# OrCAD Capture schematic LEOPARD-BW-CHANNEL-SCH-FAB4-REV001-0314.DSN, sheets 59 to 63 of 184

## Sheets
59 130_P12V_PCIE_HDD: size A3; title: P12V_PCIE_HDD
60 129_HOT SWAP CIRCUIT: size A2; title: HOT SWAP CIRCUIT
61 128_FAST PROCHOT: size Custom; title: FAST PROCHOT
62 127_INTEL I210 DECOUPLING: size A3; title: INTEL I210 DECOUPLING
63 126_INTEL I210 - RJ45: size A3; title: INTEL I210 - RJ45

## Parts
sheet 126_INTEL I210 - RJ45
C324  SCD1U16V2KX-3GP  [C402H22]
C325  SCD1U16V2KX-3GP  [C402H22]
C326  SCD1U16V2KX-3GP  [C402H22]
C329  SCD1U16V2KX-3GP  [C402H22]
C330  SCD1U16V2KX-3GP  [C402H22]
C331  SCD1U16V2KX-3GP  [C402H22]
C336  SCD1U16V2KX-3GP  [C402H22]
C337  SCD1U16V2KX-3GP  [C402H22]
C338  SCD1U16V2KX-3GP  [C402H22]
D39  PGB1010603MR-GP  [L1608-UH15]
D40  PGB1010603MR-GP  [L1608-UH15]
D41  PGB1010603MR-GP  [L1608-UH15]
D42  PGB1010603MR-GP  [L1608-UH15]
D43  PGB1010603MR-GP  [L1608-UH15]
D44  PGB1010603MR-GP  [L1608-UH15]
D45  PGB1010603MR-GP  [L1608-UH15]
D46  PGB1010603MR-GP  [L1608-UH15]
R1016  150R2J-L1-GP-U  [R402H16]
R1017  150R2J-L1-GP-U  [R402H16]
R1018  0R2J-2-GP  [R402H16]
R1019  0R2J-2-GP  [R402H16]
R1020  0R2J-2-GP  [R402H16]
R1021  0R2J-2-GP  [R402H16]
R1022  0R2J-2-GP  [R402H16]
R1023  0R2J-2-GP  [R402H16]
R1025  0R2J-2-GP  [R402H16]
R1026  0R2J-2-GP  [R402H16]
R1029  0R2J-2-GP  [R402H16]
R1030  0R2J-2-GP  [R402H16]
R1031  0R2J-2-GP  [R402H16]
R1032  0R2J-2-GP  [R402H16]
R2160  150R3J-L-GP  [R603H22]
R2161  150R3J-L-GP  [R603H22]
RJ1  RJ45-LED-12P-10-GP  [XRJH-01H-D-H71-D81-W]
sheet 127_INTEL I210 DECOUPLING
C7295  SC47U4V5MX-2-GP  [C805H58]
C7296  SC10U6D3V5KX-4GP  [C805H58]
C7297  SC10U6D3V5KX-4GP  [C805H58]
C7298  SCD1U16V2KX-3GP  [C402H22]
C7299  SCD1U16V2KX-3GP  [C402H22]
C7300  SCD1U16V2KX-3GP  [C402H22]
C7301  SCD1U16V2KX-3GP  [C402H22]
C7302  SC47U4V5MX-2-GP  [C805H58]
C7303  SC10U6D3V5KX-4GP  [C805H58]
C7304  SCD1U16V2KX-3GP  [C402H22]
C7305  SCD1U16V2KX-3GP  [C402H22]
C7306  SCD1U16V2KX-3GP  [C402H22]
C7307  SCD1U16V2KX-3GP  [C402H22]
C7308  SC10U6D3V5KX-4GP  [C805H58]
C7309  SC47U4V5MX-2-GP  [C805H58]
C7310  SC10U6D3V5KX-4GP  [C805H58]
C7311  SCD1U16V2KX-3GP  [C402H22]
C7312  SCD1U16V2KX-3GP  [C402H22]
C7313  SCD1U16V2KX-3GP  [C402H22]
C7314  SCD1U16V2KX-3GP  [C402H22]
C7315  SC10U6D3V5KX-4GP  [C805H58]
sheet 128_FAST PROCHOT
C112  SC10U6D3V5KX-4GP  [C805H58]
C316  SC100P50V2JN-3GP  [C402H22]
C356  SC100P50V2JN-3GP  [C402H22]
C371  SCD1U16V2KX-3GP  [C402H22]
C373  SC100P50V2JN-3GP  [C402H22]
C374  SCD1U16V2KX-3GP  [C402H22]
C376  SCD1U16V2KX-3GP  [C402H22]
C377  SCD1U16V2KX-3GP  [C402H22]
C378  SCD1U16V2KX-3GP  [C402H22]
C379  SCD1U16V2KX-3GP  [C402H22]
D38  TL431IDBZR-GP  [SOT-23-1H45]
Q19  2N7002-7F-GP  [SOT23DGS2D4H44]
R128  464R2F-GP  [R402H16]
R145  27KR2F-L-GP  [R402H16]
R169  11K5R2F-GP  [R402H16]
R249  3K24R2F-GP  [R402H16]
R264  7K5R2F-1-GP  [R402H16]
R266  10KR2F-2-GP  [R402H16]
R267  3K16R2F-GP  [R402H16]
R269  3K9R2F-GP  [R402H16]
R289  20KR2F-L-GP  [R402H16]
R290  10KR2F-2-GP  [R402H16]
R339  4K7R2F-GP  [R402H16]
R340  4K7R2F-GP  [R402H16]
R350  27KR2F-L-GP  [R402H16]
R380  0R2J-2-GP  [R402H16]
R403  1MR2F-GP  [R402H16]
R404  0R2J-2-GP  [R402H16]
R406  1MR2F-GP  [R402H16]
R416  10KR2F-2-GP  [R402H16]
R417  0R2J-2-GP  [R402H16]
R420  1MR2F-GP  [R402H16]
R423  10KR2F-2-GP  [R402H16]
R533  1MR2F-GP  [R402H16]
R727  100R3J-4-GP  [R603H22]
R1590  10KR2F-2-GP  [R402H16]
R1591  10KR2F-2-GP  [R402H16]
U34  LM393DR-GP  [SOIC8H69]
U50  LM393DR-GP  [SOIC8H69]
U52  NTJD4001NT1G-1-GP  [SOT-363H44]
U53  NTJD4001NT1G-1-GP  [SOT-363H44]
sheet 129_HOT SWAP CIRCUIT
C160  SC1U10V2KX-4-GP  [C402H22]
C375  SCD015U25V2KX-GP  [C402H22]
C478  SC1KP50V2KX-1GP  [C402H22]
C7272  SCD1U16V2KX-3GP  [C402H22]
C7273  SCD022U25V2KX-GP  [C402H22]
C7274  SCD1U25V3KX-GP  [C603H36]
C7275  SC1U10V2KX-4-GP  [C402H22]
C7276  SC1U10V2KX-4-GP  [C402H22]
C7277  SC1U16V3KX-5GP  [C603H36]
C7278  SCD1U25V3JX-GP  [C603H36]
C7279  SCD033U50V3KX-1GP  [C603H36]
C7316  SCD1U25V3JX-GP  [C603H36]
C7317  SCD1U25V3JX-GP  [C603H36]
D7  SMCJ13A-GP  [D795930AKH104]
JP2  FCI-CON3-S1-GP  [68001-203HLF]
P2121  0R0603-PAD-2-GP-U  [0R0603-PAD-1-U]
PC1083  SC1U25V3KX-GP  [C603H36]
PQ33  NST3904F3T5G-GP-U  [SOT-1123CBE1006H16]
Q8  PH0925CL-GP  [LFPAK-5PH48-U]
Q25  2N7002-7F-GP  [SOT23DGS2D4H44]
Q90  PH0925CL-GP  [LFPAK-5PH48-U]
R148  0R2J-2-GP  [R402H16]
R199  100R2F-L1-GP-U  [R402H14]
R250  0R2J-2-GP  [R402H16]
R255  100R2F-L1-GP-U  [R402H14]
R270  PAD-D001R2512F-6P-GP  [PAD-R2512-2032H36-6P]
R342  PAD-D001R2512F-6P-GP  [PAD-R2512-2032H36-6P]
R345  0R2J-2-GP  [R402H16]
R395  0R2J-2-GP  [R402H16]
R396  0R2J-2-GP  [R402H16]
R408  88K7R2F-GP  [R402H16]
R532  10KR2J-3-GP  [R402H16]
R674  10KR2F-2-GP  [R402H16]
R726  10KR2F-2-GP  [R402H16]
R763  6K65R2F-GP  [R402H16]
R1226  12K1R2F-L1-GP  [R402H16]
R1227  100KR2F-L1-GP  [R402H16]
R2015  10KR2F-2-GP  [R402H16]
R2098  10R2F-L-GP  [R402H14]
R2099  39K2R2F-L-GP  [R402H16]
R2100  0R2J-2-GP  [R402H16]
R2101  0R2J-2-GP  [R402H16]
R2102  26K1R2F-2-GP  [R402H16]
R2103  150KR2J-GP  [R402H16]
R2106  49K9R2F-L-GP  [R402H16]
R2107  49K9R2F-L-GP  [R402H16]
R2108  3K74R2F-GP  [R402H16]
R2109  5K49R2F-GP  [R402H16]
R2110  1KR2J-1-GP  [R402H16]
R2111  10R2J-2-GP  [R402H14]
R2112  10R2J-2-GP  [R402H14]
R2113  0R2J-2-GP  [R402H16]
R2114  0R2J-2-GP  [R402H16]
R2117  100KR2F-L1-GP  [R402H16]
R2119  10R2F-L-GP  [R402H14]
R2120  10R2F-L-GP  [R402H14]
R2121  10R2F-L-GP  [R402H14]
R2122  10R2F-L-GP  [R402H14]
R2123  10R2F-L-GP  [R402H14]
R2171  100KR2J-1-GP  [R402H16]
R2172  0R2J-2-GP  [R402H16]
R2173  30K1R2F-L-GP  [R402H16]
R2174  100KR2J-1-GP  [R402H16]
R2175  25K5R2F-GP  [R402H16]
R6611  270KR2F-GP  [R402H16]
U2  ADM1278-1ACPZ-GP  [QFN32-G3D45-UH32]
sheet 130_P12V_PCIE_HDD
C37  SCD1U25V3KX-GP  [C603H36]
C40  SCD1U25V3KX-GP  [C603H36]
C42  SCD1U16V2KX-3GP  [C402H22]
C43  SCD1U16V2KX-3GP  [C402H22]
C44  SCD1U16V2KX-3GP  [C402H22]
C47  SCD1U16V2KX-3GP  [C402H22]
C48  SCD1U16V2KX-3GP  [C402H22]
C49  SCD1U16V2KX-3GP  [C402H22]
C50  SCD1U25V3KX-GP  [C603H36]
C732  SC1U25V3KX-GP  [C603H36]
Q22  PSMN4R4-30MLC-GP  [PPAK-8P-3333-1H40]
Q31  FDMS7572S-GP  [PPAK-5PH44]
Q32  PH0925CL-GP  [LFPAK-5PH48-U]
R182  49K9R2F-L-GP  [R402H16]
R184  49K9R2F-L-GP  [R402H16]
R189  0R2J-2-GP  [R402H16]
R341  49K9R2F-L-GP  [R402H16]
R346  1KR2J-1-GP  [R402H16]
R352  0R2J-2-GP  [R402H16]
R355  1KR2J-1-GP  [R402H16]
R356  0R2J-2-GP  [R402H16]
R360  100KR2J-1-GP  [R402H16]
R425  1KR2F-3-GP  [R402H16]
R740  49K9R2F-L-GP  [R402H16]
R749  49K9R2F-L-GP  [R402H16]
R750  0R2J-2-GP  [R402H16]
R774  49K9R2F-L-GP  [R402H16]
R789  0R2J-2-GP  [R402H16]
R1212  10KR2F-2-GP  [R402H16]
R1326  0R2J-2-GP  [R402H16]
R1327  0R2J-2-GP  [R402H16]
U18  SLG55021-130010VTR-GP  [DFN8G2-G165105H32]
U26  SLG55021-130010VTR-GP  [DFN8G2-G165105H32]
U27  ADM809SARTZ-REEL7-2-GP  [SOT23-2D4-312H49]
U47  SLG55021-130010VTR-GP  [DFN8G2-G165105H32]
U177  SNLVC1G08DCKRG4-GP  [SC70-5H44]

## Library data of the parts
C324-C326 C329-C331 C336-C338 = SCD1U16V2KX-3GP: CHIP CAP C 0.1U 16V K0402 X7R; Belong: POP; Category: RJ45 CONN; GREENDFACTOR: R_SA;; POP?: NOPOP; Part Number: 78.10421.2FL; Part Type: SMD-BCG; Quotation: 15_10; Type: SMD; Vendor PN: C1005X7R104KET/GRM155R71C104KA88D/223878715649/CL05B104KO5NNNC/EMK105BJ104KV-F/C1005X7R1C104KT000F/0402B104K160CT
D39-D46 = PGB1010603MR-GP: CHIP ESD SUPP PGB1010603NR SMD; GREENDFACTOR: R2_SA;HF_SA;; POP?: NOPOP; Part Number: 69.10059.031; Part Type: DISCRET-G4; SPEC: http://wpqssvr.wistron.com.tw:7001/wpqs/servlet/COM.qpart.Attachment?PartNumber=69.10059.031
R1016 R1017 = 150R2J-L1-GP-U: CHIP RES 150 J 1/16W 0402; Category: RJ45 CONN; GREENDFACTOR: R2_SA;HF_SA;G_SA;; POP?: NOPOP; Part Number: 63.15134.1DL; Part Type: SMD-RG; SPEC: http://wpqssvr.wistron.com.tw:7001/wpqs/servlet/COM.qpart.Attachment?PartNumber=63.15134.1DL
R1018-R1023 R1025 R1026 R1029-R1032 = 0R2J-2-GP: CHIP RES 0 J 1/16W 0402; Category: LOM - i350; DESCRIPTIO: CHIP RES 0 J 1/16W 0402; GREENDFACTOR: R2_SA;HF_SA;G_SA;; POP?: NOPOP; Package Type: SMD-RG; Part Number: 63.R0034.1DL; Part Type: SMD-RG; SPEC: http://wpqssvr.wistron.com.tw:7001/wpqs/servlet/COM.qpart.Attachment?PartNumber=63.R0034.1DL; VENDORPARTNUMBER: RM04JTN0/RTT02000JTH/RR0510X-000-XN/RC0402JR-070RL/WR04X000 PTL; Vendor PN: RM04JTN0/RTT02000JTH/RR0510X-000-XN/RC0402JR-070RL/WR04X000 PTL
R2160 R2161 = 150R3J-L-GP: CHIP RES 150 J 1/10W 0603; Category: RJ45 CONN; DESCRIPTIO: CHIP RES 150 J 1/10W 0603; GREENDFACTOR: R2_SA;HF_SA;G_SA;; Module: IO_REAR USB / LOM; POP?: NOPOP; Part Number: 63.15133.15L; Part Type: SMD-RG
RJ1 = RJ45-LED-12P-10-GP: SKT RJ45+LED XRJH-01H-D-H71-D81-W; Category: RJ45 CONN; GREENDFACTOR: R2_C;; POP?: NOPOP; Part Number: 22.10277.R91; Part Type: SOCKET-G4; SPEC: http://wpqssvr.wistron.com.tw:7001/wpqs/servlet/COM.qpart.Attachment?PartNumber=22.10277.R91
C7295 C7302 C7309 = SC47U4V5MX-2-GP: CHIP CAP C 47U 4V M0805 X6S; GREENDFACTOR: R2_SA;HF_SA;G_SA;; POP?: NOPOP; Part Number: 78.4761T.81L; Part Type: SMD-BCG3; SPEC: http://wpqssvr.wistron.com.tw:7001/wpqs/servlet/COM.qpart.Attachment?PartNumber=78.4761T.81L
C7296 C7297 C7303 C7308 C7310 C7315 = SC10U6D3V5KX-4GP: CHIP CAP C 10U 6.3V K0805 X7R; GREENDFACTOR: R2_SA;HF_SA;G_SA;; POP?: NOPOP; Part Number: 78.10620.21L; Part Type: SMD-BCG; SPEC: http://wpqssvr.wistron.com.tw:7001/wpqs/servlet/COM.qpart.Attachment?PartNumber=78.10620.21L
C7298-C7301 C7304-C7307 C7311-C7314 = SCD1U16V2KX-3GP: CHIP CAP C 0.1U 16V K0402 X7R; Category: CLK GEN; GREENDFACTOR: R_SA;HF_SA;G_SA;; POP?: NOPOP; Part Number: 78.10421.2FL; Quotation: 13_8; Type: SMD
C112 = SC10U6D3V5KX-4GP: CHIP CAP C 10U 6.3V K0805 X7R; GREENDFACTOR: R2_SA;HF_SA;G_SA;; Package Type: SMD-BCG; Part Number: 78.10620.21L; Part Type: SMD-BCG; SPEC: http://wpqssvr.wistron.com.tw:7001/wpqs/servlet/COM.qpart.Attachment?PartNumber=78.10620.21L
C316 C356 C373 = SC100P50V2JN-3GP: CHIP CAP 100P50V J0402 NPO(ROH; CATEGORIES: CAP_Small; Category: BMC; GREENDFACTOR: R2_SA;HF_SA;G_SA;; Level: SMD; MAIN_SOURCE: M; Part Number: 78.10134.1FL; Part Type: SMD-BCG; SPEC: http://wpqssvr.wistron.com.tw:7001/wpqs/servlet/COM.qpart.Attachment?PartNumber=78.10134.1FL; Status: POP
C371 C374 C376-C379 = SCD1U16V2KX-3GP: CHIP CAP C 0.1U 16V K0402 X7R; CATEGORIES: CAP_1.xV; GREENDFACTOR: R2_SA;HF_SA;G_SA;; MAIN_SOURCE: M; Part Number: 78.10421.2FL; Part Type: SMD-BCG; SPEC: http://wpqssvr.wistron.com.tw:7001/wpqs/servlet/COM.qpart.Attachment?PartNumber=78.10421.2FL
D38 = TL431IDBZR-GP: IC A.R TL431BIDBZR SOT-23 (GP); GREENDFACTOR: R2_SA;G_SA;; Part Number: 74.00431.J31; Part Type: DISCRET-G; SPEC: http://wpqssvr.wistron.com.tw:7001/wpqs/servlet/COM.qpart.Attachment?PartNumber=74.00431.J31
Q19 Q25 = 2N7002-7F-GP: FET MOS 2N7002-7-F NC SOT-23; GREENDFACTOR: R2_SA;HF_SA;G_SA;; Part Number: 84.27002.N31; Part Type: DISCRET-G; SPEC: http://wpqssvr.wistron.com.tw:7001/wpqs/servlet/COM.qpart.Attachment?PartNumber=84.27002.N31
R128 = 464R2F-GP: CHIP RES 464 F 1/16W 0402; GREENDFACTOR: R2_SA;HF_SA;G_SA;; Part Number: 64.46405.6DL; Part Type: SMD-RG3; SPEC: http://wpqssvr.wistron.com.tw:7001/wpqs/servlet/COM.qpart.Attachment?PartNumber=64.46405.6DL
R145 R350 = 27KR2F-L-GP: CHIP RES 27K F 1/16W 0402; GREENDFACTOR: R2_SA;HF_SA;G_SA;; Part Number: 64.27025.6DL; Part Type: SMD-RG; SPEC: http://wpqssvr.wistron.com.tw:7001/wpqs/servlet/COM.qpart.Attachment?PartNumber=64.27025.6DL
R169 = 11K5R2F-GP: CHIP RES 11.5K F 1/16W 0402; GREENDFACTOR: R2_SA;HF_SA;G_SA;; Part Number: 64.11525.6DL; Part Type: RCL_GP; SPEC: http://wpqssvr.wistron.com.tw:7001/wpqs/servlet/COM.qpart.Attachment?PartNumber=64.11525.6DL
R249 = 3K24R2F-GP: CHIP RES 3.24K F 1/16W 0402; GREENDFACTOR: R2_SA;HF_SA;G_SA;; Part Number: 64.32415.6DL; Part Type: RCL_GP; SPEC: http://wpqssvr.wistron.com.tw:7001/wpqs/servlet/COM.qpart.Attachment?PartNumber=64.32415.6DL
R264 = 7K5R2F-1-GP: CHIP RES 7.5K F 1/16W 0402; Category: PCH; Part Number: 64.75015.6DL; Part Type: SMD-RG
R266 R290 R416 R726 R1590 R1591 = 10KR2F-2-GP: CHIP RES 10K F 1/16W 0402; Category: internal conn; DESCRIPTIO: CHIP RES 10K F 1/16W 0402; GREENDFACTOR: R2_SA;HF_SA;G_SA;; Package Type: SMD-RG; Part Number: 64.10025.6DL; Part Type: SMD-RG; SPEC: http://wpqssvr.wistron.com.tw:7001/wpqs/servlet/COM.qpart.Attachment?PartNumber=64.10025.6DL; VENDORPARTNUMBER: RM04FTN1002 / RTT021002FTH / RR0510S-103-FN / RC0402FR-0710KL/WR04X1002FTL
R267 = 3K16R2F-GP: CHIP RES 3.16K F 1/16W 0402; GREENDFACTOR: R2_SA;HF_SA;G_SA;; Part Number: 64.31615.6DL; Part Type: SMD-RG; SPEC: http://wpqssvr.wistron.com.tw:7001/wpqs/servlet/COM.qpart.Attachment?PartNumber=64.31615.6DL
R269 = 3K9R2F-GP: CHIP RES 3.9K F 1/16W 0402; GREENDFACTOR: R2_SA;HF_SA;G_SA;; Part Number: 64.39015.6DL; Part Type: RCL_GP; SPEC: http://wpqssvr.wistron.com.tw:7001/wpqs/servlet/COM.qpart.Attachment?PartNumber=64.39015.6DL
R289 = 20KR2F-L-GP: CHIP RES 20K F 1/16W 0402; GREENDFACTOR: R2_SA;HF_SA;G_SA;; Part Number: 64.20025.6DL; Part Type: SMD-RG; SPEC: http://wpqssvr.wistron.com.tw:7001/wpqs/servlet/COM.qpart.Attachment?PartNumber=64.20025.6DL
R339 R340 = 4K7R2F-GP: CHIP RES 4.7K F 1/16W 0402; Category: LOM - i350; DESCRIPTIO: CHIP RES 4.7K F 1/16W 0402; GREENDFACTOR: R2_SA;HF_SA;G_SA;; Package Type: RCL_GP; Part Number: 64.47015.6DL; Part Type: RCL_GP; SPEC: http://wpqssvr.wistron.com.tw:7001/wpqs/servlet/COM.qpart.Attachment?PartNumber=64.47015.6DL; VENDORPARTNUMBER: RM04FTN4701/RTT024701FTH/RR0510S-472-FN/RC0402FR-074K7L/WR04X4701FTL
R380 R404 R417 = 0R2J-2-GP: CHIP RES 0 J 1/16W 0402; GREENDFACTOR: R2_SA;HF_SA;G_SA;; Part Number: 63.R0034.1DL; Part Type: SMD-RG; SPEC: http://wpqssvr.wistron.com.tw:7001/wpqs/servlet/COM.qpart.Attachment?PartNumber=63.R0034.1DL
R403 R406 R420 R533 = 1MR2F-GP: CHIP RES 1M F 1/16W 0402; GREENDFACTOR: R2_SA;HF_SA;G_SA;; Part Number: 64.10045.6DL; Part Type: RCL_GP; SPEC: http://wpqssvr.wistron.com.tw:7001/wpqs/servlet/COM.qpart.Attachment?PartNumber=64.10045.6DL
R423 R674 = 10KR2F-2-GP: CHIP RES 10K F 1/16W 0402; Category: internal conn; DESCRIPTIO: CHIP RES 10K F 1/16W 0402; GREENDFACTOR: R2_SA;HF_SA;G_SA;; POP?: NOPOP; Package Type: SMD-RG; Part Number: 64.10025.6DL; Part Type: SMD-RG; SPEC: http://wpqssvr.wistron.com.tw:7001/wpqs/servlet/COM.qpart.Attachment?PartNumber=64.10025.6DL; VENDORPARTNUMBER: RM04FTN1002 / RTT021002FTH / RR0510S-103-FN / RC0402FR-0710KL/WR04X1002FTL
R727 = 100R3J-4-GP: CHIP RES 100 J 1/10W 0603(ROHS; GREENDFACTOR: R2_SA;HF_SA;G_SA;; Part Number: 63.10133.15L; Part Type: SMD-RG; SPEC: http://wpqssvr.wistron.com.tw:7001/wpqs/servlet/COM.qpart.Attachment?PartNumber=63.10133.15L
U34 U50 = LM393DR-GP: IC V.C LM393DR SO-N 8P (ROHS); GREENDFACTOR: R2_SA;HF_SA;; Part Number: 74.00393.H21; Part Type: DISCRET-G; SPEC: http://wpqssvr.wistron.com.tw:7001/wpqs/servlet/COM.qpart.Attachment?PartNumber=74.00393.H21
U52 U53 = NTJD4001NT1G-1-GP: IC MOSFET NTJD4001NT1G NC SOT-363 6P; GREENDFACTOR: R2_SA;; Part Number: 75.04001.07C; Part Type: DISCRET-G5; SPEC: http://wpqssvr.wistron.com.tw:7001/wpqs/servlet/COM.qpart.Attachment?PartNumber=75.04001.07C
C160 = SC1U10V2KX-4-GP: CHIP CAP C 1U 10V K 0402 X6S; GREENDFACTOR: R2_SA;HF_SA;; POP?: NOPOP; Part Number: 78.10523.8FL; Part Type: SMD-BCG6; SPEC: http://wpqssvr.wistron.com.tw:7001/wpqs/servlet/COM.qpart.Attachment?PartNumber=78.10523.8FL
C375 = SCD015U25V2KX-GP: CHIP CAP C 0.015U 25V K0402 X7; GREENDFACTOR: R2_SA;HF_SA;G_SA;; POP?: NOPOP; Part Number: 78.15322.2FL; Part Type: SMD-BCG; SPEC: http://wpqssvr.wistron.com.tw:7001/wpqs/servlet/COM.qpart.Attachment?PartNumber=78.15322.2FL
C478 = SC1KP50V2KX-1GP: CHIP CAP 1000P50V K0402 X7R(RO; Category: Powervill; GREENDFACTOR: R2_SA;HF_SA;G_SA;; Package Type: SMD-BCG; Part Number: 78.10224.2FL; Quotation: 9_7; Type: SMD
C7272 = SCD1U16V2KX-3GP: CHIP CAP C 0.1U 16V K0402 X7R; CATEGORIES: CAP_1.xV; GREENDFACTOR: R2_SA;HF_SA;G_SA;; MAIN_SOURCE: M; POP?: NOPOP; Package Type: SMD-BCG; Part Number: 78.10421.2FL; SPEC: http://wpqssvr.wistron.com.tw:7001/wpqs/servlet/COM.qpart.Attachment?PartNumber=78.10421.2FL
C7273 = SCD022U25V2KX-GP: CHIP CAP C 0.022U 25V K0402 X7R; GREENDFACTOR: R2_SA;HF_SA;G_SA;; Part Number: 78.22322.2FL; Part Type: SMD-BCG; SPEC: http://wpqssvr.wistron.com.tw:7001/wpqs/servlet/COM.qpart.Attachment?PartNumber=78.22322.2FL
C7274 = SCD1U25V3KX-GP: CHIP CAP C 0.1U 25V K0603 X7R; CATEGORIES: CAP_1.xV; GREENDFACTOR: R2_SA;R_SA;HF_SA;G_SA;; MAIN_SOURCE: M; POP?: NOPOP; Package Type: RCL_GP; Part Number: 78.10422.2BL; SPEC: http://wpqssvr.wistron.com.tw:7001/wpqs/servlet/COM.qpart.Attachment?PartNumber=78.10422.2BL
C7275 C7276 = SC1U10V2KX-4-GP: CHIP CAP C 1U 10V K 0402 X6S; GREENDFACTOR: R2_SA;HF_SA;; Part Number: 78.10523.8FL; Part Type: SMD-BCG6; SPEC: http://wpqssvr.wistron.com.tw:7001/wpqs/servlet/COM.qpart.Attachment?PartNumber=78.10523.8FL
C7277 = SC1U16V3KX-5GP: CHIP CAP C 1U 16V K0603 X7R; CATEGORIES: CAP_Small; GREENDFACTOR: R2_SA;HF_SA;G_SA;; MAIN_SOURCE: M; Package Type: SMD-BCG3; Part Number: 78.10521.2BL; SPEC: http://wpqssvr.wistron.com.tw:7001/wpqs/servlet/COM.qpart.Attachment?PartNumber=78.10521.2BL
C7278 = SCD1U25V3JX-GP: CHIP CAP C 0.1U 25V J0603 X7R; GREENDFACTOR: R2_SA;HF_SA;G_SA;; Package Type: SMD-BCG2; Part Number: 78.10432.2BL; SPEC: http://wpqssvr.wistron.com.tw:7001/wpqs/servlet/COM.qpart.Attachment?PartNumber=78.10432.2BL
C7279 = SCD033U50V3KX-1GP: CHIP CAP 0.033U 50V K0603 X7R; GREENDFACTOR: R2_SA;HF_SA;G_SA;; Package Type: SMD-BCG; Part Number: 78.33324.2BL; SPEC: http://wpqssvr.wistron.com.tw:7001/wpqs/servlet/COM.qpart.Attachment?PartNumber=78.33324.2BL
C7316 C7317 = SCD1U25V3JX-GP: CHIP CAP C 0.1U 25V J0603 X7R; GREENDFACTOR: R2_SA;HF_SA;G_SA;; POP?: NOPOP; Package Type: SMD-BCG2; Part Number: 78.10432.2BL; SPEC: http://wpqssvr.wistron.com.tw:7001/wpqs/servlet/COM.qpart.Attachment?PartNumber=78.10432.2BL
D7 = SMCJ13A-GP: DIODE TVS SMCJ13A SMB; GREENDFACTOR: R2_SA;; Package Type: DISCRET-G5; Part Number: 83.00013.0AG; SPEC: http://wpqssvr.wistron.com.tw:7001/wpqs/servlet/COM.qpart.Attachment?PartNumber=83.00013.0AG
JP2 = FCI-CON3-S1-GP: HEAD ML 1R3P ST 68001-203HLF; Category: PCH; GREENDFACTOR: R_SA;; Green Factor: R_SA;; Part Number: 21.61084.103; Part Type: CONN-G4; ROOM: IMMv2; S/D: DIP; SPEC: http://wpqssvr.wistron.com.tw:7001/wpqs/servlet/COM.qpart.Attachment?PartNumber=21.61084.103; Vender: FCI
P2121 = 0R0603-PAD-2-GP-U: PAD WITH WIRE RES 0 0603; GREENDFACTOR: R_C;; Package Type: SMD-RG4; Part Number: ZZ.00PAD.M21; SPEC: http://wpqssvr.wistron.com.tw:7001/wpqs/servlet/COM.qpart.Attachment?PartNumber=ZZ.00PAD.M21
PC1083 = SC1U25V3KX-GP: CHIP CAP C 1U 25V K0603 X7R; GREENDFACTOR: R2_SA;HF_SA;G_SA;; Package Type: SMD-BCG; Part Number: 78.10522.2BL; SPEC: http://wpqssvr.wistron.com.tw:7001/wpqs/servlet/COM.qpart.Attachment?PartNumber=78.10522.2BL
PQ33 = NST3904F3T5G-GP-U: XTOR NST3904F3T5G NPN SOT-1123; GREENDFACTOR: R2_SA;; Package Type: DISCRET-G5; Part Number: 84.N3904.011; SPEC: http://wpqssvr.wistron.com.tw:7001/wpqs/servlet/COM.qpart.Attachment?PartNumber=84.N3904.011
Q8 Q32 Q90 = PH0925CL-GP: FET MOS PH0925CL NC LFPAK; GREENDFACTOR: R2_SA;; Part Number: 84.00925.03N; Part Type: DISCRET-G7; SPEC: http://wpqssvr.wistron.com.tw:7001/wpqs/servlet/COM.qpart.Attachment?PartNumber=84.00925.03N
R148 R189 R352 R356 R750 R789 R1326 R2100 R2101 R2114 R2172 = 0R2J-2-GP: CHIP RES 0 J 1/16W 0402; Category: BMC; DESCRIPTIO: CHIP RES 0 J 1/16W 0402; GREENDFACTOR: R2_SA;HF_SA;G_SA;; Package Type: SMD-RG; Part Number: 63.R0034.1DL; Part Type: SMD-RG; SPEC: http://wpqssvr.wistron.com.tw:7001/wpqs/servlet/COM.qpart.Attachment?PartNumber=63.R0034.1DL; VENDORPARTNUMBER: RM04JTN0/RTT02000JTH/RR0510X-000-XN/RC0402JR-070RL/WR04X000 PTL
R199 R255 = 100R2F-L1-GP-U: CHIP RES 100 F 1/16W 0402; GREENDFACTOR: R2_SA;HF_SA;G_SA;; Package Type: SMD-RG; Part Number: 64.10005.6DL; SPEC: http://wpqssvr.wistron.com.tw:7001/wpqs/servlet/COM.qpart.Attachment?PartNumber=64.10005.6DL
R250 = 0R2J-2-GP: CHIP RES 0 J 1/16W 0402; Category: HOTPLUG_CONTROL; GREENDFACTOR: R2_SA;HF_SA;G_SA;; POP?: NOPOP; Package Type: SMD-RG; Part Number: 63.R0034.1DL; Part Type: SMD-RG; SPEC: http://wpqssvr.wistron.com.tw:7001/wpqs/servlet/COM.qpart.Attachment?PartNumber=63.R0034.1DL
R270 R342 = PAD-D001R2512F-6P-GP: CHIP RES 0.001 F 3W 2512 SPECIAL SYMBOL; GREENDFACTOR: R2_C;; POP?: 064.R0015.0C71; Part Number: ZZ.R0015.001; Part Type: DISCRET-G9; SPEC: http://wpqssvr.wistron.com.tw:7001/wpqs/servlet/COM.qpart.Attachment?PartNumber=ZZ.R0015.001
R345 R395 R396 = 0R2J-2-GP: CHIP RES 0 J 1/16W 0402; Category: HOTPLUG_CONTROL; GREENDFACTOR: R2_SA;HF_SA;G_SA;; Package Type: SMD-RG; Part Number: 63.R0034.1DL; Part Type: SMD-RG; SPEC: http://wpqssvr.wistron.com.tw:7001/wpqs/servlet/COM.qpart.Attachment?PartNumber=63.R0034.1DL
R408 = 88K7R2F-GP: CHIP RES 88.7K F 1/16W 0402; GREENDFACTOR: R2_SA;HF_SA;G_SA;; Part Number: 64.88725.6DL; Part Type: SMD-RG3; SPEC: http://wpqssvr.wistron.com.tw:7001/wpqs/servlet/COM.qpart.Attachment?PartNumber=64.88725.6DL
R532 = 10KR2J-3-GP: CHIP RES 10K J 1/16W 0402; Category: HOTPLUG; GREENDFACTOR: R2_SA;HF_SA;G_SA;; POP?: NOPOP; Package Type: SMD-RG; Part Number: 63.10334.1DL; Part Type: SMD-RG; SPEC: http://wpqssvr.wistron.com.tw:7001/wpqs/servlet/COM.qpart.Attachment?PartNumber=63.10334.1DL
R763 = 6K65R2F-GP: CHIP RES 6.65K F 1/16W 0402; GREENDFACTOR: R2_SA;HF_SA;G_SA;; Part Number: 64.66515.6DL; Part Type: RCL_GP; SPEC: http://wpqssvr.wistron.com.tw:7001/wpqs/servlet/COM.qpart.Attachment?PartNumber=64.66515.6DL
R1226 = 12K1R2F-L1-GP: CHIP RES 12.1K F 1/16W 0402; GREENDFACTOR: R2_SA;HF_SA;G_SA;; Part Number: 64.12125.6DL; Part Type: SMD-RG; SPEC: http://wpqssvr.wistron.com.tw:7001/wpqs/servlet/COM.qpart.Attachment?PartNumber=64.12125.6DL
R1227 R2117 = 100KR2F-L1-GP: CHIP RES 100K F 1/16W 0402; GREENDFACTOR: R2_SA;HF_SA;G_SA;; Part Number: 64.10035.6DL; Part Type: SMD-RG; SPEC: http://wpqssvr.wistron.com.tw:7001/wpqs/servlet/COM.qpart.Attachment?PartNumber=64.10035.6DL
R2015 = 10KR2F-2-GP: CHIP RES 10K F 1/16W 0402; Category: 240VA; GREENDFACTOR: R2_SA;R_SA;HF_SA;G_SA;; Level: SMD; Part Number: 64.10025.6DL; Part Type: SMD-RG; SPEC: http://wpqssvr.wistron.com.tw:7001/wpqs/servlet/COM.qpart.Attachment?PartNumber=64.10025.6DL; Status: NOPOP
R2098 = 10R2F-L-GP: CHIP RES 10 F 1/16W 0402; Category: HOTPLUG_CONTROL; GREENDFACTOR: R2_SA;HF_SA;G_SA;; Package Type: SMD-RG; Part Number: 64.10R05.6DL; Part Type: SMD-RG; SPEC: http://wpqssvr.wistron.com.tw:7001/wpqs/servlet/COM.qpart.Attachment?PartNumber=64.10R05.6DL
R2099 = 39K2R2F-L-GP: CHIP RES 39.2K F 1/16W 0402; GREENDFACTOR: R2_SA;HF_SA;G_SA;; Package Type: SMD-RG; Part Number: 64.39225.6DL; SPEC: http://wpqssvr.wistron.com.tw:7001/wpqs/servlet/COM.qpart.Attachment?PartNumber=64.39225.6DL
R2102 = 26K1R2F-2-GP: CHIP RES 26.1K F 1/16W 0402; GREENDFACTOR: R2_SA;HF_SA;G_SA;; Package Type: SMD-RG; Part Number: 64.26125.6DL; SPEC: http://wpqssvr.wistron.com.tw:7001/wpqs/servlet/COM.qpart.Attachment?PartNumber=64.26125.6DL
R2103 = 150KR2J-GP: CHIP RES 150K J 1/16W 0402; GREENDFACTOR: R2_SA;HF_SA;G_SA;; Part Number: 63.15434.1DL; Part Type: RCL_GP; SPEC: http://wpqssvr.wistron.com.tw:7001/wpqs/servlet/COM.qpart.Attachment?PartNumber=63.15434.1DL
R182 R184 R341 R740 R749 R774 R2106 R2107 = 49K9R2F-L-GP: CHIP RES 49.9K F 1/16W 0402; Category: HOTPLUG_CONTROL; GREENDFACTOR: R2_SA;R_SA;HF_SA;G_SA;; POP?: POP; Package Type: SMD-RG; Part Number: 64.49925.6DL; Part Type: SMD-RG; SPEC: http://wpqssvr.wistron.com.tw:7001/wpqs/servlet/COM.qpart.Attachment?PartNumber=64.49925.6DL
R2108 = 3K74R2F-GP: CHIP RES 3.74K F 1/16W 0402; GREENDFACTOR: R2_SA;HF_SA;G_SA;; Package Type: RCL_GP; Part Number: 64.37415.6DL; SPEC: http://wpqssvr.wistron.com.tw:7001/wpqs/servlet/COM.qpart.Attachment?PartNumber=64.37415.6DL
R2109 = 5K49R2F-GP: CHIP RES 5.49K F 1/16W 0402; GREENDFACTOR: R2_SA;HF_SA;G_SA;; Part Number: 64.54915.6DL; Part Type: SMD-RG; SPEC: http://wpqssvr.wistron.com.tw:7001/wpqs/servlet/COM.qpart.Attachment?PartNumber=64.54915.6DL
R2110 = 1KR2J-1-GP: CHIP RES 1K J 1/16W 0402; GREENDFACTOR: R2_SA;HF_SA;G_SA;; Part Number: 63.10234.1DL; Part Type: SMD-RG; SPEC: http://wpqssvr.wistron.com.tw:7001/wpqs/servlet/COM.qpart.Attachment?PartNumber=63.10234.1DL
R2111 R2112 = 10R2J-2-GP: CHIP RES 10 J 1/16W 0402; Category: HOTPLUG_CONTROL; GREENDFACTOR: R2_SA;HF_SA;G_SA;; Package Type: SMD-RG; Part Number: 63.10034.1DL; Part Type: SMD-RG; SPEC: http://wpqssvr.wistron.com.tw:7001/wpqs/servlet/COM.qpart.Attachment?PartNumber=63.10034.1DL
R2113 = 0R2J-2-GP: CHIP RES 0 J 1/16W 0402; Category: HOTPLUG_CONTROL; DESCRIPTIO: CHIP RES 0 J 1/16W 0402; GREENDFACTOR: R2_SA;HF_SA;G_SA;; Magnum_%: +/-5%; Magnum_Package: 0402; Magnum_Value: 0ohm; POP?: NOPOP; Package Type: SMD-RG; Part Number: 63.R0034.1DL; Part Type: SMD-RG; SPEC: http://wpqssvr.wistron.com.tw:7001/wpqs/servlet/COM.qpart.Attachment?PartNumber=63.R0034.1DL
R2119-R2123 = 10R2F-L-GP: CHIP RES 10 F 1/16W 0402; GREENDFACTOR: R2_SA;HF_SA;G_SA;; Package Type: SMD-RG; Part Number: 64.10R05.6DL; SPEC: http://wpqssvr.wistron.com.tw:7001/wpqs/servlet/COM.qpart.Attachment?PartNumber=64.10R05.6DL
R2171 R2174 = 100KR2J-1-GP: CHIP RES 100K J 1/16W 0402; GREENDFACTOR: R2_SA;HF_SA;G_SA;; Package Type: SMD-RG; Part Number: 63.10434.1DL; SPEC: http://wpqssvr.wistron.com.tw:7001/wpqs/servlet/COM.qpart.Attachment?PartNumber=63.10434.1DL
R2173 = 30K1R2F-L-GP: CHIP RES 30.1K F 1/16W 0402; GREENDFACTOR: R2_SA;HF_SA;G_SA;; Part Number: 64.30125.6DL; Part Type: SMD-RG; SPEC: http://wpqssvr.wistron.com.tw:7001/wpqs/servlet/COM.qpart.Attachment?PartNumber=64.30125.6DL
R2175 = 25K5R2F-GP: CHIP RES 25.5K F 1/16W 0402; GREENDFACTOR: R2_SA;HF_SA;G_SA;; Part Number: 64.25525.6DL; Part Type: SMD-RG; SPEC: http://wpqssvr.wistron.com.tw:7001/wpqs/servlet/COM.qpart.Attachment?PartNumber=64.25525.6DL
R6611 = 270KR2F-GP: CHIP RES 270K F 1/16W 0402; GREENDFACTOR: R2_SA;HF_SA;G_SA;; Part Number: 64.27035.6DL; Part Type: RCL_GP; SPEC: http://wpqssvr.wistron.com.tw:7001/wpqs/servlet/COM.qpart.Attachment?PartNumber=64.27035.6DL
U2 = ADM1278-1ACPZ-GP: IC SWAP CTRL ADM1278-1ACPZ LFCSP 32P; GREENDFACTOR: R2_SA;; Part Number: 74.01278.A7Z; Part Type: DISCRET-GA1; SPEC: http://wpqssvr.wistron.com.tw:7001/wpqs/servlet/COM.qpart.Attachment?PartNumber=74.01278.A7Z
C37 C40 C50 = SCD1U25V3KX-GP: CHIP CAP C 0.1U 25V K0603 X7R; CATEGORIES: CAP_1.xV; GREENDFACTOR: R2_SA;R_SA;HF_SA;G_SA;; MAIN_SOURCE: M; Package Type: RCL_GP; Part Number: 78.10422.2BL; SPEC: http://wpqssvr.wistron.com.tw:7001/wpqs/servlet/COM.qpart.Attachment?PartNumber=78.10422.2BL
C42-C44 C47-C49 = SCD1U16V2KX-3GP: CHIP CAP C 0.1U 16V K0402 X7R; Belong: POP; CATEGORIES: CAP_1.xV; Category: P12V_PCIE/HDD; GREENDFACTOR: R2_SA;HF_SA;G_SA;; MAIN_SOURCE: M; Part Number: 78.10421.2FL; Part Type: SMD-BCG; SPEC: http://wpqssvr.wistron.com.tw:7001/wpqs/servlet/COM.qpart.Attachment?PartNumber=78.10421.2FL
C732 = SC1U25V3KX-GP: CHIP CAP C 1U 25V K0603 X7R; GREENDFACTOR: R2_SA;HF_SA;G_SA;; Part Number: 78.10522.2BL; Part Type: SMD-BCG; SPEC: http://wpqssvr.wistron.com.tw:7001/wpqs/servlet/COM.qpart.Attachment?PartNumber=78.10522.2BL
Q22 = PSMN4R4-30MLC-GP: FET MOS NPN PSMN4R4-30MLC LFPAK33 4P; GREENDFACTOR: R2_C;; Part Number: 084.4R430.003N; Part Type: DISCRET-GA1; SPEC: http://wpqssvr.wistron.com.tw:7001/wpqs/servlet/COM.qpart.Attachment?PartNumber=084.4R430.003N
Q31 = FDMS7572S-GP: FET MOS FDMS7572S NC POWER56 8P; GREENDFACTOR: R2_SA;; POP?: POP(NMOS); Package Type: DISCRET-G5; Part Number: 84.07572.037; SPEC: http://wpqssvr.wistron.com.tw:7001/wpqs/servlet/COM.qpart.Attachment?PartNumber=84.07572.037
R346 = 1KR2J-1-GP: CHIP RES 1K J 1/16W 0402; Belong: POP; Category: P12V_PCIE/HDD; POP?: NOPOP; Part Number: 63.10234.1DL; Part Type: SMD-RG; Status: NPOP
R355 = 1KR2J-1-GP: CHIP RES 1K J 1/16W 0402; Belong: POP; Category: PWR_MOS_P5V_P3V; POP?: NOPOP; Part Number: 63.10234.1DL; Part Type: SMD-RG; Status: NPOP
R360 = 100KR2J-1-GP: CHIP RES 100K J 1/16W 0402; Belong: POP; Category: PWR_MOS_P5V_P3V; GREENDFACTOR: R2_SA;HF_SA;G_SA;; POP?: NOPOP; Part Number: 63.10434.1DL; Part Type: SMD-RG; SPEC: http://wpqssvr.wistron.com.tw:7001/wpqs/servlet/COM.qpart.Attachment?PartNumber=63.10434.1DL
R425 = 1KR2F-3-GP: CHIP RES 1K F 1/16W 0402; GREENDFACTOR: R2_SA;HF_SA;G_SA;; Part Number: 64.10015.6DL; Part Type: SMD-RG; SPEC: http://wpqssvr.wistron.com.tw:7001/wpqs/servlet/COM.qpart.Attachment?PartNumber=64.10015.6DL
R1212 = 10KR2F-2-GP: CHIP RES 10K F 1/16W 0402; Category: Logic; GREENDFACTOR: R2_SA;R_SA;HF_SA;G_SA;; Level: SMD; POP?: NOPOP; Part Number: 64.10025.6DL; Part Type: SMD-RG; SPEC: http://wpqssvr.wistron.com.tw:7001/wpqs/servlet/COM.qpart.Attachment?PartNumber=64.10025.6DL; Status: POP
R1327 = 0R2J-2-GP: CHIP RES 0 J 1/16W 0402; Category: BMC; DESCRIPTIO: CHIP RES 0 J 1/16W 0402; GREENDFACTOR: R2_SA;HF_SA;G_SA;; POP?: NOPOP; Package Type: SMD-RG; Part Number: 63.R0034.1DL; Part Type: SMD-RG; SPEC: http://wpqssvr.wistron.com.tw:7001/wpqs/servlet/COM.qpart.Attachment?PartNumber=63.R0034.1DL; VENDORPARTNUMBER: RM04JTN0/RTT02000JTH/RR0510X-000-XN/RC0402JR-070RL/WR04X000 PTL
U18 U26 U47 = SLG55021-130010VTR-GP: IC DRIVER SLG55021-130010VTR TDFN 8PIN; GREENDFACTOR: R2_C;; POP?: 74.55021.AE3; Package Type: DISCRET-G8; Part Number: 74.55021.0E3; SPEC: http://wpqssvr.wistron.com.tw:7001/wpqs/servlet/COM.qpart.Attachment?PartNumber=74.55021.0E3
U27 = ADM809SARTZ-REEL7-2-GP: IC RESET ADM809SARTZ-REEL7 SOT-23; GREENDFACTOR: R2_C;; POP?: NOPOP; Part Number: 74.AD809.A7B; Part Type: DISCRET-G5; SPEC: http://wpqssvr.wistron.com.tw:7001/wpqs/servlet/COM.qpart.Attachment?PartNumber=74.AD809.A7B
U177 = SNLVC1G08DCKRG4-GP: IC CMOS SN74LVC1G08DCKRG4 DCK; Alternate: 73.01G08.CAH,73.01G08.L04,73.01G08.DAH; Category: CPU SIDE BAND; DESCRIPTIO: IC CMOS SN74LVC1G08DCKRG4 DCK; GREENDFACTOR: R2_SA;HF_SA;G_SA;; Package Type: TTL-G; Part Number: 73.01G08.DHG; Part Type: TTL-G; SPEC: http://wpqssvr.wistron.com.tw:7001/wpqs/servlet/COM.qpart.Attachment?PartNumber=73.01G08.DHG; VENDORPARTNUMBER: SN74LVC1G08DCKRG4

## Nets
AGND_CURRENT_MON: C112.2 C160.2 C316.2 C356.2 C373.2 C374.2 C376.2 C377.2 C378.2 C379.2 C7272.2 C7273.2 C7275.2 C7276.2 C7277.2 C7278.2 C7316.2 C7317.2 D38.3 P2121.1 PC1083.2 Q19.S R128.2 R249.2 R267.2 R269.2 R408.2 R532.1 R1226.2 R2102.2 R2103.2 R2108.2 R2109.2 R2113.2 R2172.1 R2173.2 R2175.2 R6611.2 U2.22(GND) U2.33(GND) U34.4(GND) U50.4(GND) U52.1(S1) U52.4(S2) U53.1(S1) U53.4(S2)
GND: C37.2 C40.2 C42.2 C43.2 C44.2 C47.2 C48.2 C49.2 C50.2 C324.2 C325.2 C326.2 C329.2 C330.2 C331.2 C336.2 C337.2 C338.2 C371.2 C478.2 C732.2 C7274.2 C7279.2 C7295.2 C7296.2 C7297.2 C7298.2 C7299.2 C7300.2 C7301.2 C7302.2 C7303.2 C7304.2 C7305.2 C7306.2 C7307.2 C7308.2 C7309.2 C7310.2 C7311.2 C7312.2 C7313.2 C7314.2 C7315.2 D7.A D39.2 D40.2 D41.2 D42.2 D43.2 D44.2 D45.2 D46.2 P2121.2 R255.1 R360.2 R425.2 R763.2 R2121.2 RJ1.13 RJ1.14 U2.23(PGND) U18.4(GND) U18.9(NC#9) U26.4(GND) U27.1(GND) U47.4(GND) U47.9(NC#9) U177.3(GND) ; also on sheet 1 2 3 4 5 6 7 8 9 10 11 12 13 14 15 16 17 18 19 20 21 22 23 24 25 26 27 28 29 30 31 32 33 34 35 36 37 38 39 44 46 47 49 50 51 52 53 54 55 56 57 58 64 65 66 69 70 71 73 74 75 76 78 79 80 81 82 83 84 86 87 88 89 90 91 92 93 94 95 96 97 98 99 100 101 102 103 104 105 106 107 108 109 110 111 112 113 114 115 116 117 118 119 128 129 138 139 159 160 161 166 168 169 170 171 172 173 174 175 176 177 180 181 182 183 184
P0V9_I210: C7309.1 C7310.1 C7311.1 C7312.1 C7313.1 C7314.1 C7315.1 ; also on sheet 64
P1V5_I210: C7302.1 C7303.1 C7304.1 C7305.1 C7306.1 C7307.1 C7308.1 ; also on sheet 64
P2V5_REF: C112.1 C377.1 C378.1 C379.1 D38.1(CATHODE) D38.2 R289.1 R727.1 U34.2(1IN-) U34.5(2IN+) U50.2(1IN-)
P3V3_STBY: C732.1 C7295.1 C7296.1 C7297.1 C7298.1 C7299.1 C7300.1 C7301.1 R184.1 R290.1 R416.1 R423.1 R727.2 R774.1 R1212.1 R1590.1 R1591.1 R2015.2 R2160.1 R2161.1 U177.5(VCC) ; also on sheet 2 3 5 6 8 9 10 11 12 15 16 17 20 21 22 25 26 27 30 31 33 34 35 37 38 39 45 47 49 50 51 52 54 55 64 65 66 69 70 71 72 73 74 76 79 83 84 87 88 89 90 91 92 93 94 95 96 97 98 99 159 161 166 168 173 174 176 177 179 180 182 183 184
P5V: Q22.1(S#1) Q22.2(S#2) Q22.3(S#3) U26.6(S) ; also on sheet 45 66 69 76 80 82 176
P5V_STBY: C37.1 C40.1 C50.1 C371.1 C374.1 Q22.5(D#5) Q22.6(D#6) Q22.7(D#7) Q22.8(D#8) R182.1 R339.2 R340.2 R341.1 R740.1 R749.1 U18.1(VCC) U26.1(VCC) U26.5(D) U34.8(VCC) U47.1(VCC) U50.8(VCC) ; also on sheet 4 5 6 8 14 15 19 20 24 25 29 30 33 34 37 38 65 69 76 95
P12V_FAN: Q31.1 Q31.2 Q31.3 U18.6(S) ; also on sheet 66
P12V_MAIN: C7274.1 D7.K R270.1 R270.3 R342.2 R342.4 R726.1 R2098.1 R2106.1 R2107.1 ; also on sheet 53 93
P12V_PCIE_HDD: C47.1 C48.1 C49.1 Q32.1(S#1) Q32.2(S#2) Q32.3(S#3) U47.6(S) ; also on sheet 76 80 82 94
P12V_PG: R184.2 R1326.2 U27.3(VCC) U47.8(PG)
P12V_SENSE_OUT: R266.1 R345.1 R350.1
P12V_SENSE_OUT_CMP: C373.1 R266.2 R267.1 R420.2 U50.3(1IN+)
P12V_STBY: C42.1 C43.1 C44.1 Q8.1(S#1) Q8.2(S#2) Q8.3(S#3) Q31.5 Q31.6 Q31.7 Q31.8 Q32.5(D) Q90.1(S#1) Q90.2(S#2) Q90.3(S#3) R345.2 R1227.1 R2099.1 R2110.2 U18.5(D) U47.5(D) ; also on sheet 2 3 4 7 9 10 11 12 13 17 18 22 23 27 28 32 36 75 95 104 105 106 107 108 109 110 111 112 113 114 115 116 117 118 119
CPLD_PS_P5V_EN: R355.2 R356.2 R360.1 U26.2(ON)
CSOUT_CMP: C356.1 R145.1 R169.1 R533.2 U34.6(2IN-)
CSOUT_CMP_R: Q19.D R423.2 R533.1
CURRENT_ALERT_N: R417.2 ; also on sheet 52
CURRENT_MODE: Q19.G R417.1 R1591.2 U34.7(2OUT)
DRIVER_G: Q31.4 U18.7(G)
DRIVER_G_1: Q32.4(G) U47.7(G)
DRIVER_G_2: Q22.4(G) U26.7(G)
DRIVER_SHD_N: R740.2 U18.3(SHDN#)
DRIVER_SHD_N_1: R182.2 U47.3(SHDN#)
DRIVER_SHD_N_2: R341.2 U26.3(SHDN#)
FAN1_EN_DRIVER: U18.2(ON) U177.4(Y)
FAN1_EN_DRIVER_1: R189.2 U47.2(ON)
FAN_PWR_PG: R749.2 U18.8(PG)
FM_PS_EN: R352.1 R425.1 R750.1 ; also on sheet 51 93
FM_PS_EN_R: R189.1 R346.2 R352.2
FM_SLPS3_N: R346.1 R355.1 ; also on sheet 51 52 74 90
IRQ_SML1_PMBUS_ALERT_N: R148.2 ; also on sheet 52 54 74 90
LED_MDI0_1G_N: R1016.1 ; also on sheet 64
LED_MDI0_1G_N_R: C331.1 R1016.2 RJ1.D3
LED_MDI0_100M_1G_N: R2160.2 RJ1.D4
LED_MDI0_100M_N: R1017.1 ; also on sheet 64
LED_MDI0_100M_N_R: C336.1 R1017.2 RJ1.D5
LED_MDI0_ACT: C338.1 R2161.2 RJ1.D2
LED_MDI0_LINK_N: C337.1 RJ1.D1 ; also on sheet 64
MB0_12V_CTRL_GATE1: Q8.4(G) R2111.1
MB0_12V_CTRL_GATE2: Q90.4(G) R2112.1
MB0_412W: JP2.1 R726.2 R763.1
MB0_575W: JP2.3 R2121.1
MB0_CM_ADR1_R: R2103.1 U2.7(ADR1)
MB0_CM_ADR2_R: R2172.2 U2.8(ADR2)
MB0_CM_FAULT_N_R: R2015.1 U2.6(FAULT#) ; also on sheet 177
MB0_CM_GATE: R2114.1 U2.24(GATE)
MB0_CM_GATE_R: C7279.1 R2111.2 R2112.2 R2114.2
MB0_CM_OV_R: C7275.1 R2106.2 R2108.1 U2.32(OV)
MB0_CM_SENSE_N: R395.1 R2122.2 R2123.2 U2.27(HS-)
MB0_CM_SENSE_P: R396.1 R2119.2 R2120.2 U2.28(HS+)
MB0_CM_SENSE_R1_N: R270.6 R2122.1
MB0_CM_SENSE_R1_P: R270.5 R2119.1
MB0_CM_SENSE_R2_N: R342.5 R2123.1
MB0_CM_SENSE_R2_P: R342.6 R2120.1
MB0_CM_UV_R: C7276.1 R2107.2 R2109.1 U2.31(UV)
MB0_CM_VOUT_R: C7272.1 R2110.1 U2.20(VOUT)
MB0_CSOUT_N: R145.2 U2.19(CSOUT)
MB0_CURMON_ALERT1_R_N: R148.1 U2.13(GPO1/ALERT1#/CONV)
MB0_CURMON_ALERT2_R_N: R250.2 U2.14(GPO2/ALERT2#)
MB0_HS_ENABLE: U2.12(ENABLE) ; also on sheet 93
MB0_ISET_R: C7278.1 Q25.D R408.1 R2117.2 U2.3(ISET)
MB0_ISTART_R: C7317.1 R2174.2 R2175.1 U2.4(ISTART)
MB0_MO_N: C375.1 R395.2 U2.26(MO-)
MB0_MO_P: C375.2 R396.2 U2.29(MO+)
MB0_P12V_HS: PC1083.1 R2098.2 U2.30(VCC)
MB0_P12V_MAIN_R: Q8.5(D) Q90.5(D) R270.2 R270.4 R342.1 R342.3
MB0_P12V_PWGIN_R: R1226.1 R1227.2 U2.21(PWGIN)
MB0_P12V_PWRGOOD: C160.1 R2099.2 R2102.1 U2.18(PWRGD) ; also on sheet 4
MB0_PMBUS_PCH_SML1CLK_R: R2100.1 U2.16(SCL)
MB0_PMBUS_PCH_SML1DATA_R: R2101.1 U2.15(SDA)
MB0_PSET_R: C7316.1 R2171.2 R2173.1 U2.1(PSET)
MB0_RETRY_R: R532.2 U2.17(RETRY#)
MB0_SPISS_PD: R674.2 R2113.1 U2.9(NIC#9)
MB0_TEMP: C478.1 R199.1 U2.25(TEMP)
MB0_TIME_R: C7273.1 U2.5(TIMER) U50.6(2IN-)
MB0_VCAP_R: C7277.1 R674.1 R2117.1 R2171.1 R2174.1 U2.2(VCAP)
MNG_RX_DN: R1031.1 ; also on sheet 93
MNG_RX_DP: R1029.1 ; also on sheet 93
MNG_TX_DN: R1030.1 ; also on sheet 93
MNG_TX_DP: R1032.1 ; also on sheet 93
NIC0_CT_POWER: C324.1 C325.1 C326.1 C329.1 C330.1 RJ1.1 RJ1.6 RJ1.7 RJ1.12
NIC0_MDI0_N0: R1023.2 ; also on sheet 64
NIC0_MDI0_N0_R: D41.1 R1023.1 RJ1.10
NIC0_MDI0_N1: R1025.2 ; also on sheet 64
NIC0_MDI0_N1_R: D40.1 R1025.1 RJ1.5
NIC0_MDI0_N2: R1019.2 R1030.2 ; also on sheet 64
NIC0_MDI0_N2_R: D45.1 R1019.1 RJ1.2
NIC0_MDI0_N3: R1020.2 R1031.2 ; also on sheet 64
NIC0_MDI0_N3_R: D44.1 R1020.1 RJ1.9
NIC0_MDI0_P0: R1026.2 ; also on sheet 64
NIC0_MDI0_P0_R: D39.1 R1026.1 RJ1.11
NIC0_MDI0_P1: R1022.2 ; also on sheet 64
NIC0_MDI0_P1_R: D42.1 R1022.1 RJ1.4
NIC0_MDI0_P2: R1021.2 R1032.2 ; also on sheet 64
NIC0_MDI0_P2_R: D43.1 R1021.1 RJ1.3
NIC0_MDI0_P3: R1018.2 R1029.2 ; also on sheet 64
NIC0_MDI0_P3_R: D46.1 R1018.1 RJ1.8
POWER_FAIL: R250.1 ; also on sheet 54 91
POWER_FAIL_N: R404.2 ; also on sheet 48 52 54 93 177
POWER_SET: JP2.2 Q25.G U52.5(G2)
PQ33_B: PQ33.B PQ33.C R199.2
PQ33_E: PQ33.E R255.2
PWRGD_P5V: R774.2 U26.8(PG) ; also on sheet 51
PWRGD_PS_PWROK: R356.1 R1326.1 R1327.1 ; also on sheet 51 65
PWRGD_PS_PWROK_DLY: R1327.2 U27.2(RESET#)
Q25_S: Q25.S R6611.1
SMB_PMBUS_BMC_STBY_LVC3_CLK: R2100.2 ; also on sheet 74 77 90 162
SMB_PMBUS_BMC_STBY_LVC3_DATA: R2101.2 ; also on sheet 74 77 90 162
TIMER_ALERT_CPLD_N: R290.2 R403.1 U50.7(2OUT) ; also on sheet 52
TIMER_CMP: C376.1 R269.1 R289.2 R403.2 U50.5(2IN+)
U52_2: R339.1 U52.2(G1) U52.3(D2)
U52_6: R169.2 R249.1 U52.6(D1)
U53_2: R340.1 U53.2(G1) U53.3(D2)
U177_1: R750.2 U177.1(A)
U177_2: R789.2 U177.2(B)
UV_10D5V_N: R404.1 R416.2 R420.1 U50.1(1OUT)
UV_FAN_ALERT_N: R789.1 R1212.2 ; also on sheet 52
UV_FPH_LEVEL_SEL: U53.5(G2) ; also on sheet 177
VOLTAGE_ALERT_N: R380.2 ; also on sheet 52 177
VOLTAGE_MODE: R380.1 R406.1 R1590.2 U34.1(1OUT)
VOLTAGE_SET: C316.1 R264.2 R350.2 R406.2 U34.3(1IN+)
VOLTAGE_SET_R: R128.1 R264.1 U53.6(D1)

Not connected (* = marked no-connect by the designer): RJ1 NP1* NP2*; U2 10(NIC#10)* 11(NIC#11)*; U26 9(NC#9)*

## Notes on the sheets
sheet 59
- P12V PCIE HDD
- FAB1 REV013 20150413
- Place close to Q18.
- change to 74.55021.AE3
- FAB1 REV003 20150318
- FAB1 REV006 20150324
- FAB1 REV005 20150323
- FAB1 REV003 20150318
- FAB1 REV001 20150316
- Delete components
- FAB1 20150303
- FAB1 REV011 20150407
- FAB2 REV001 20150703
- Change to 084.4R430.003N
- 10 mils
sheet 60
- Layout Note: please close to Q8 or Q90
- HOT SWAP CIRCUIT
- FAB1 20150313
- MB have PWRGD delay on
  P5V_AUX and P3V3_AUX
- For voltage rating,
  PC35 change from: 78.10521.2BL  to
- SA.9
- From PCH SML1
- FAB1 REV027 20150508
- FAB1 20150312
- FAB1 REV015 20150416
- PWRGOOD assert when:
  VOUT x (R1226/(R1226+R1227)  > 1.0
- FAB1 20150211
- FAB1 REV027 20150508
- Please place R395,R396 close to U2
- FAB1 20150303
- FAB1 20150217
- PWGIN = 1V
- Set Vout > 9.25V
- Del:R56 R115 R63 R116
- Delete components
- FAB1 REV026 20150506
- FAB1 REV009 20150327
- 48.8A
- Ton = 1V*(0.01uF/60uA) = 166.67 us
  Toff= 0.2V*(0.01u/2uA)  = 5ms
- FAB1 REV027 20150508
- ADDRESS : 0X22
- FAB1 REV005 20150323
- UV = [RUV1(49.9K) + RUV2(5.49K) / RUV2] * 1V = 10.08V
- Tolerance ( 10.27 ~ 9.9V )
- FAB1 REV013 20150413
- OV = [ROV1(49.9K) + ROV2(3.74K) / ROV2] * 1V = 14.34V
- Tolerance ( 14.61 ~ 14.07V )
- FAB1 20150311
- FAB1 REV003 20150318
- OV triggerred at 14.34V
  OV specification 13.2V
- UV triggerred at 10.08V
  UV specification: protect under 10V
- Delete components
- FAB1 REV012 20150409
- 2.7V
- This should be placed
  as close as possible
  to IC and GND
  directly to IC or
  small signal IC gnd plane.
- FAB1 REV027 20150508
- Choose R1 = 100K, R2 = 88.7K ohm
- VISET = 2.7V x (R2 / (R1+R2)) = 1269mV
- FAB1 REV013 20150413
- I_TRIP_CB = ((Viset/50)-VCBOS)/Rsense =49A  (VCBOS=0.88mV)
- Remove R783
- I_TRIP = (Viset/50)/Rsense = 50.76A
- 2.7V
- I_TRIP_CB Tolerance ( 48.46 ~ 49.54A )
- PSET set to 200W
  FETPowerLimit = ( Vpset x 8 ) / ( 50 x Rsense )
  Vpset = ( 200 x 50 x 0.5m )  / 8 = 0.625V
- FAB1 REV014 20150416
- Change to 84.27002.N31
- Default is short 2-3
- 12.5v * (6.65k / 16.65k) = 5V
- Startup_CB set to 20A
- 2.7V
- Vistart = 2.7V*[25.5/(100+25.5)] = 0.5486V
  Startup_CB=[(Vistart/50)-0.88mV] / Rsense
- =[(Vistart/50)-0.88mV] / Rsense = 20.184A
- FAB1 REV012 20150409
- Choose R1 = 100K, R2 = 88.7K ohm, R3 = 270K ohm
- VISET = 2.7V x (R2//R3) / (R1+(R2//R3)) = 1081mV
- I_TRIP_CB = ((Viset/50)-VCBOS)/Rsense =41.47A  (VCBOS=0.88mV)
- I_TRIP = (Viset/50)/Rsense = 43.23A
- I_TRIP_CB Tolerance ( 40.96 ~ 41.99A )
sheet 61
- FAST PROCHOT
- FAB2 REV001 20150701
- FAB1 REV020 20150423
- Vsense voltage =
  11.5V x (7.5k/ 34.5k) = 2.5V
- Tolerance ( 11.68 ~ 11.32V )
- Vsense voltage =
  11V x (7.964k/ 34.964k) = 2.505V
- FAB1 REV005 20150323
- Tolerance ( 11.14 ~ 10.8V )
- FAB1 REV014 20150416
- FAB1 REV005 20150323
- FAB1 REV014 20150416
- FAB1 REV014 20150416
- I(throttle) = 47.9A.
- FAB1 REV013 20150413
- Vsense = 47.9A * 0.5m ohm = 23.95mV
- FAB1 REV006 20150324
- CSOUT = 350 * Vsense = 8.38V
- Tolerance ( 47.6A ~ 48.34A )
- FAB1 REV002 20150317
- FAB1 REV006 20150324
- I(throttle) = 40.6A.
- FAB1 REV013 20150413
- Vsense = 40.6A * 0.5m ohm = 20.3mV
- Change to 75.04001.07C
- CSOUT = 350 * Vsense = 7.1V
- Tolerance ( 40.38A ~ 40.84A )
- FAB1 REV013 20150413
- Change to 75.04001.07C
- FAB1 REV004 20150320
- FAB1 REV013 20150414
- Vsense voltage =
  10.5V x (3.16k/13.16k) = 2.52V
- Tolerance ( 10.57 ~ 10.25V )
- 2.5V * (3.9/23.9) = 0.407V
- FAB1 REV013 20150413
- FAB1 REV014 20150416
- FAB1 REV014 20150415
sheet 62
- INTEL I210 DECOUPLING
- VDD3P3 DECOUPLING
- CAD NOTE:
  PLACE ALL CAPS
  BSC STYLE
  NEAR TO PIN
  VDD3P3
- VDD1P5 DECOUPLING
- Place this cap. close to
- VDD1P5_OUT
- CAD NOTE:
  PLACE ALL CAPS
  BSC STYLE
  NEAR TO PIN
  VDD1P5
- VDD0P9 DECOUPLING
- Place this cap. close to
- VDD0P9_OUT
- CAD NOTE:
  PLACE ALL CAPS
  BSC STYLE
  NEAR TO PIN
  VDD1P5
sheet 63
- INTEL I210 RJ45
- Layout Note:
  1) The in-pair trace length matching must be within 10 mils.
  2) The pair to pair length matching is not as critical as the
     in-pair length matching but it should be within 2 inches.
  3) Do not use serpentine routing (zig zag of shorter trace)
     to match the trace lengths. Serpentine routing to the
     RJ-45 connector which connects to long out-of-system
     unshielded cables can contribute to radiated EMI and
     can decrease immunity to ESD.
- Layout Note:
  Provide a shape for MDI_XF_BIAS.
- The I210's output buffers are internally biased.
  The System Side Center tap should not be
  connected to a power supply.
- Non-pop these resistors when using I210-AS
- FAB1 20150206
- Provide a separate chassis ground to
  connect the shroud of the RJ-45 connector
  and to terminate the line side of the
  magnetics module.
- Left
- Right
- LED_LAN0_1G_N
- YELLOW
- P3V3_STBY
- Speed
- LED2
- Status
- LED1
- D3
- D4
- 1000M
- Yellow
- Link
- Green
- LED_LAN0_100M_N
- Green
- P3V3_STBY
- 100M
- Green
- Active
- Blink
- D5
- D4
- 10M
- None
- Green
- LED_LAN0_LINK_N
- LED_LAN0_ACT
- Pop these resistors when using I210-AS
- D1
- D2
- LED cueent = [ (3.3 - 1.8) V / 300 ohm = 5mA
  VF = 1.8V (normal) and IF= 5mA (normal)
